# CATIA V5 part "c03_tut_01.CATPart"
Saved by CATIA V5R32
Part number: c03tut1
Bounding box of the stored display mesh (mm): x -1 to 1, y -100 to 100, z -100 to 100
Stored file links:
  D:\PROJECTS\Project 2022\CATIA V5 6R 2022\Resources\Tutorial Files\c03_catia_v5_6r2021_tut\c03_tut_01.CATPart
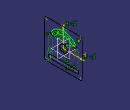
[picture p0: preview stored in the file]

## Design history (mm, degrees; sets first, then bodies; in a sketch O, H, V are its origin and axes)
Body1 (main body)
  Sketch1 on yz-plane, origin (0, 0, 0), H (0, 1, 0), V (0, 0, 1)
    line L1 (100, 90) -> (100, -90)
    line L2 (90, -100) -> (-90, -100)
    line L3 (-100, -90) -> (-100, 90)
    line L4 (-90, 100) -> (90, 100)
    arc A1 centre (90, 90) radius 10 from (100, 90) to (90, 100) ccw
    arc A2 centre (-90, 90) radius 10 from (-100, 90) to (-90, 100) cw
    arc A3 centre (90, -90) radius 10 from (100, -90) to (90, -100) cw
    arc A4 centre (-90, -90) radius 10 from (-90, -100) to (-100, -90) cw
    circle A5 centre (0, 0) radius 20
    construction line L5 (-70, -70) -> (70, -70)
    line L6 (-70, -60) -> (70, -60)
    line L7 (70, -80) -> (-70, -80)
    arc A6 centre (70, -70) radius 10 from (70, -60) to (70, -80) cw
    arc A7 centre (-70, -70) radius 10 from (-70, -80) to (-70, -60) cw
    construction arc A8 centre (0, 0) radius 70 from (57.3406, 40.1504) to (-57.3406, 40.1504) ccw
    construction line L8 (0, 0) -> (57.3406, 40.1504)
    construction line L9 (0, 0) -> (-57.3406, 40.1504)
    arc A9 centre (57.3406, 40.1504) radius 10 from (65.5322, 45.8861) to (49.1491, 34.4146) cw
    arc A10 centre (-57.3406, 40.1504) radius 10 from (-49.1491, 34.4146) to (-65.5322, 45.8861) cw
    arc A11 centre (0, 0) radius 60 from (49.1491, 34.4146) to (-49.1491, 34.4146) ccw
    arc A12 centre (0, 0) radius 80 from (-65.5322, 45.8861) to (65.5322, 45.8861) cw
    radius A1 = 10
    radius A2 = 10
    radius A3 = 10
    radius A4 = 10
    distance L5 L6 = 10
    radius A8 = 70
    angle L8 L9 = 110
    radius A10 = 10
    vertical: L1 V, L3 V
    horizontal: L2 H, L4 H, L5 H
    equidistance: L1 L3 O, L2 L4 O
    tangency: A1 L1, A1 L4, A2 L3, A2 L4, A3 L1, A3 L2, A4 L2, A4 L3, A6 L6, A7 L6, A6 L7, A7 L7, A11 A10, A10 A12, A12 A9, A9 A11
    concentricity: A11 O, A12 O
